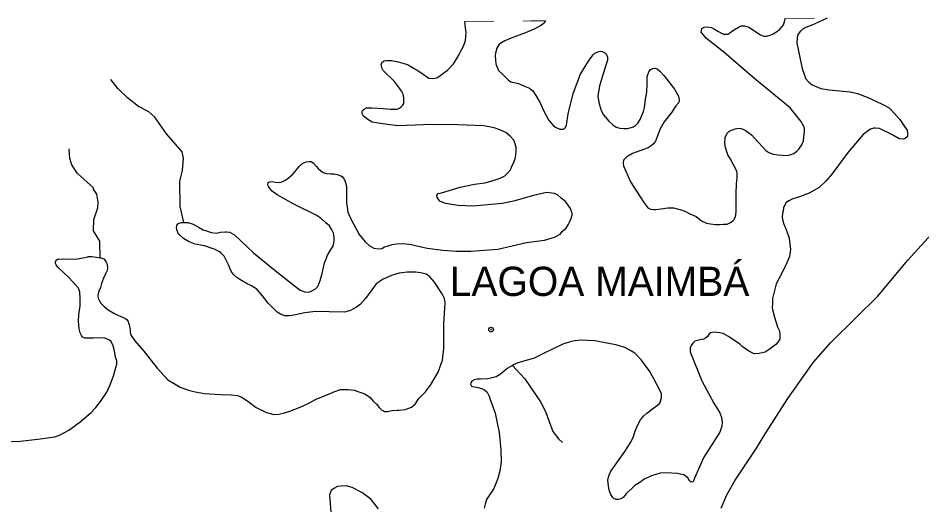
# Model space of a CAD drawing. Extents: x 317.8 to 344.1, y 7676.8 to 7704.8.
# Drawn here: x 334.107 to 337.199, y 7703.031 to 7704.701 of the extents above; entities that cross this region are included whole.
import ezdxf
from ezdxf.enums import TextEntityAlignment as Align

# ---------------------------------------------------------------- set-up
doc = ezdxf.new("R2010")
doc.units = 0
doc.header["$LTSCALE"] = 0.032
doc.header["$PDMODE"] = 32
doc.header["$PDSIZE"] = 0.016
doc.linetypes.add('SHORT_DASHED', pattern=[2.7, 1.5, -1.2])
for name, color, linetype, lineweight in [('2', 7, 'Continuous', 25), ('62', 7, 'SHORT_DASHED', 13), ('7', 7, 'Continuous', 25)]:
    doc.layers.add(name, color=color, linetype=linetype, lineweight=lineweight)
doc.layers.add('61', color=7, linetype='Continuous')

msp = doc.modelspace()

# ---------------------------------------------------------------- linework, layer by layer
at = {"layer": '2'}
for points in [[(335.6243, 7704.5923), (335.6305, 7704.6048), (335.6378, 7704.6236), (335.6389, 7704.6371), (335.6399, 7704.6507), (335.6378, 7704.6674), (335.6349, 7704.6886)], [(335.9111, 7704.6913), (335.9062, 7704.6832), (335.898, 7704.6761), (335.8742, 7704.6638), (335.8433, 7704.6496), (335.8, 7704.6337), (335.7717, 7704.6231), (335.7584, 7704.6152), (335.7514, 7704.609), (335.7443, 7704.5975), (335.7399, 7704.5807), (335.739, 7704.571), (335.7408, 7704.5445), (335.7505, 7704.5215), (335.7638, 7704.5083), (335.7841, 7704.4879), (335.7929, 7704.4826), (335.8194, 7704.4765), (335.8397, 7704.4676), (335.8565, 7704.4605), (335.868, 7704.4517), (335.8777, 7704.4358), (335.8927, 7704.4102), (335.9051, 7704.3819), (335.921, 7704.3519), (335.9387, 7704.3324), (335.9475, 7704.3262), (335.9599, 7704.3209), (335.9652, 7704.3209), (335.9714, 7704.3209), (335.9758, 7704.3227), (335.9793, 7704.3262), (335.9829, 7704.3342), (335.9891, 7704.3731), (336.0058, 7704.4429), (336.0315, 7704.5083), (336.0509, 7704.5401), (336.0633, 7704.5595), (336.0739, 7704.5745), (336.0801, 7704.5807), (336.0898, 7704.5851), (336.0995, 7704.5869), (336.1048, 7704.586), (336.1145, 7704.5816), (336.1198, 7704.5763), (336.1234, 7704.5666), (336.1234, 7704.5569), (336.1189, 7704.5427), (336.096, 7704.4685), (336.0907, 7704.4332), (336.0942, 7704.412), (336.1013, 7704.3846), (336.1092, 7704.3695), (336.1278, 7704.3475), (336.141, 7704.336), (336.1534, 7704.3271), (336.1658, 7704.3236), (336.1799, 7704.3227), (336.1923, 7704.3227), (336.2091, 7704.3271), (336.2179, 7704.3324), (336.2267, 7704.3413), (336.2356, 7704.3536), (336.24, 7704.3651), (336.2462, 7704.381), (336.2497, 7704.3952), (336.2532, 7704.4226), (336.2577, 7704.4473), (336.2594, 7704.4747), (336.2594, 7704.4941), (336.2594, 7704.5012), (336.2647, 7704.5162), (336.27, 7704.5242), (336.278, 7704.5286), (336.285, 7704.5295), (336.2939, 7704.5268), (336.3027, 7704.5189), (336.3169, 7704.503), (336.3531, 7704.457), (336.3663, 7704.4332), (336.369, 7704.4208), (336.3672, 7704.412), (336.3575, 7704.4005), (336.3434, 7704.3784), (336.3177, 7704.3457), (336.3036, 7704.3218), (336.2948, 7704.298), (336.2877, 7704.2794), (336.2806, 7704.2706), (336.2727, 7704.2635), (336.263, 7704.2564), (336.2091, 7704.237), (336.1896, 7704.2264), (336.1826, 7704.2193), (336.1781, 7704.214)], [(336.8746, 7704.7006), (336.8303, 7704.6799), (336.7938, 7704.6653), (336.7823, 7704.6548), (336.775, 7704.6444), (336.7719, 7704.634), (336.7709, 7704.6152), (336.7896, 7704.5277), (336.7969, 7704.5048), (336.8011, 7704.4933), (336.8126, 7704.4808), (336.824, 7704.4724), (336.8532, 7704.4599), (336.8824, 7704.4547), (336.9178, 7704.4516), (336.9533, 7704.4485), (336.9793, 7704.4422), (337.0116, 7704.4297), (337.0398, 7704.4172), (337.0679, 7704.4036), (337.0867, 7704.3932), (337.0919, 7704.3891), (337.1232, 7704.3536), (337.1398, 7704.3296), (337.1482, 7704.3171), (337.1503, 7704.3067), (337.1503, 7704.3025), (337.1503, 7704.2952), (337.1419, 7704.289), (337.1346, 7704.2859), (337.1211, 7704.2869), (337.1023, 7704.2984), (337.0825, 7704.3088), (337.0742, 7704.313), (337.0606, 7704.3192), (337.0544, 7704.3223), (337.0408, 7704.3244), (337.0346, 7704.3234), (337.0231, 7704.3203), (337.0116, 7704.313), (336.9981, 7704.3025), (336.947, 7704.2421), (336.8907, 7704.166), (336.872, 7704.1441), (336.848, 7704.1212), (336.8136, 7704.1014), (336.7802, 7704.0889), (336.7573, 7704.0816), (336.7438, 7704.0753), (336.7344, 7704.0691), (336.7302, 7704.0618), (336.726, 7704.0513), (336.724, 7704.0409), (336.7219, 7704.0336), (336.7208, 7704.018), (336.7229, 7704.0065), (336.7271, 7703.9951), (336.7344, 7703.9773), (336.7448, 7703.9471), (336.75, 7703.9085), (336.7458, 7703.8846), (336.7365, 7703.8627), (336.7208, 7703.8304), (336.701, 7703.7918), (336.6875, 7703.7407), (336.6875, 7703.7261), (336.6864, 7703.7084), (336.6948, 7703.6771), (336.7052, 7703.6438), (336.7114, 7703.6302), (336.7125, 7703.6188), (336.7125, 7703.6021), (336.7062, 7703.5917), (336.6989, 7703.5833), (336.676, 7703.5667), (336.6625, 7703.5573), (336.6427, 7703.5531), (336.6249, 7703.5521), (336.6072, 7703.5604), (336.5843, 7703.5771), (336.5759, 7703.5844), (336.5374, 7703.6115), (336.5197, 7703.6209), (336.5072, 7703.624), (336.4873, 7703.6261), (336.4769, 7703.624), (336.4707, 7703.6198), (336.4655, 7703.6115), (336.4582, 7703.6052), (336.4519, 7703.6021), (336.4404, 7703.6), (336.43, 7703.5979), (336.4227, 7703.5948), (336.4154, 7703.5885), (336.4102, 7703.5802)], [(336.7136, 7704.6629), (336.7206, 7704.6717), (336.7251, 7704.6779), (336.7295, 7704.6876), (336.7313, 7704.6993)], [(336.2612, 7704.0515), (336.2709, 7704.047), (336.2806, 7704.0453), (336.2877, 7704.0453), (336.3071, 7704.0479), (336.3301, 7704.0515), (336.3487, 7704.0515), (336.3707, 7704.0453), (336.3875, 7704.04), (336.4052, 7704.0311), (336.4264, 7704.0214), (336.445, 7704.0073), (336.4626, 7703.9993), (336.4759, 7703.9967), (336.4927, 7703.994), (336.5068, 7703.994), (336.5201, 7703.9949), (336.5333, 7703.9958), (336.5448, 7704.0011), (336.5528, 7704.0064), (336.5554, 7704.0099), (336.5616, 7704.0205), (336.5634, 7704.0364), (336.5642, 7704.0992), (336.5651, 7704.1345), (336.5669, 7704.1531), (336.5669, 7704.1681), (336.566, 7704.1769), (336.543, 7704.2202), (336.536, 7704.2308), (336.5333, 7704.2397), (336.5263, 7704.2609), (336.5254, 7704.2759), (336.5263, 7704.2874), (336.5263, 7704.2918), (336.5333, 7704.3068), (336.5386, 7704.313), (336.5422, 7704.3148), (336.5607, 7704.3218), (336.5722, 7704.3236), (336.581, 7704.3227), (336.5943, 7704.3174), (336.604, 7704.3103), (336.6164, 7704.3006), (336.665, 7704.2476), (336.6756, 7704.2405), (336.6906, 7704.2344), (336.7074, 7704.2326), (336.7348, 7704.2308), (336.748, 7704.2326), (336.7604, 7704.237), (336.771, 7704.245), (336.7781, 7704.252), (336.7887, 7704.2671), (336.794, 7704.2803), (336.7957, 7704.2927), (336.7975, 7704.313), (336.7975, 7704.3218), (336.7957, 7704.3298), (336.7851, 7704.3475), (336.748, 7704.3934), (336.6287, 7704.4915), (336.521, 7704.5842), (336.4618, 7704.6302), (336.4494, 7704.6452), (336.4441, 7704.6523), (336.445, 7704.6585), (336.4467, 7704.6646), (336.4494, 7704.6673), (336.4547, 7704.67), (336.4662, 7704.6708), (336.4794, 7704.6682), (336.49, 7704.6629), (336.5033, 7704.6549), (336.5112, 7704.6496), (336.5201, 7704.6461), (336.5289, 7704.6452), (336.5377, 7704.6461), (336.5422, 7704.6496), (336.551, 7704.6567), (336.5607, 7704.6629), (336.5713, 7704.67), (336.5802, 7704.6735), (336.5837, 7704.6744), (336.5925, 7704.6744), (336.6075, 7704.67), (336.6164, 7704.6638), (336.6314, 7704.6532), (336.6464, 7704.6434), (336.6579, 7704.639), (336.6685, 7704.639), (336.68, 7704.6417), (336.6906, 7704.647), (336.7047, 7704.6558), (336.7136, 7704.6629)], [(335.5513, 7704.5037), (335.5763, 7704.5225), (335.5962, 7704.5444), (335.6076, 7704.5621), (335.616, 7704.5756), (335.6243, 7704.5923)], [(335.6556, 7703.9033), (335.7483, 7703.9096), (335.8463, 7703.9325), (335.9078, 7703.9409), (335.9422, 7703.9513), (335.961, 7703.9617), (335.9693, 7703.9711), (335.9818, 7703.9815), (335.9891, 7703.993), (335.9933, 7704.0023), (335.9985, 7704.0128), (336.0027, 7704.0263), (336.0027, 7704.0315), (335.9964, 7704.0493), (335.9797, 7704.0732), (335.9651, 7704.0847), (335.9526, 7704.0962), (335.9422, 7704.1003), (335.9151, 7704.1035), (335.8703, 7704.0941), (335.8015, 7704.0743), (335.7629, 7704.0659), (335.6639, 7704.0566), (335.6118, 7704.0597), (335.5701, 7704.0659), (335.5629, 7704.0683), (335.5492, 7704.0743), (335.544, 7704.0816), (335.5409, 7704.0878), (335.5399, 7704.0941), (335.5399, 7704.0951), (335.544, 7704.1003), (335.5555, 7704.1024), (335.6191, 7704.1222), (335.6681, 7704.1326), (335.7035, 7704.1368), (335.7327, 7704.1451), (335.7556, 7704.1524), (335.7723, 7704.1608), (335.7817, 7704.1702), (335.7911, 7704.1816), (335.7952, 7704.191), (335.8025, 7704.2077), (335.8077, 7704.2192), (335.8098, 7704.2317), (335.8109, 7704.2452), (335.8109, 7704.2588), (335.8067, 7704.2734), (335.8025, 7704.2827), (335.79, 7704.2963), (335.7754, 7704.3088), (335.7546, 7704.3182), (335.7358, 7704.3255), (335.7004, 7704.3317), (335.6107, 7704.3349), (335.5221, 7704.3359), (335.4075, 7704.3317), (335.37, 7704.3359), (335.3178, 7704.3442), (335.3001, 7704.3557), (335.2876, 7704.3661), (335.2845, 7704.3724), (335.2845, 7704.3786), (335.2855, 7704.3838), (335.2907, 7704.3891), (335.2991, 7704.3932), (335.3178, 7704.3932), (335.3554, 7704.3911), (335.3814, 7704.3891), (335.4033, 7704.3891), (335.4117, 7704.3922), (335.4179, 7704.3974), (335.4231, 7704.4026), (335.4263, 7704.4078), (335.4263, 7704.4162), (335.4263, 7704.4276), (335.4242, 7704.4401), (335.42, 7704.4495), (335.4117, 7704.461), (335.395, 7704.4839), (335.3564, 7704.5214), (335.3512, 7704.5298), (335.3502, 7704.5371), (335.3491, 7704.5433), (335.3533, 7704.5506), (335.3595, 7704.5548), (335.3679, 7704.5558), (335.3846, 7704.5558), (335.4075, 7704.5506), (335.4388, 7704.5412), (335.4815, 7704.5162), (335.5117, 7704.4954), (335.5263, 7704.4933), (335.5399, 7704.4964), (335.5513, 7704.5037)], [(334.6737, 7704.0013), (334.6872, 7704.0013), (334.706, 7703.9951), (334.7258, 7703.9836), (334.7394, 7703.9763), (334.7519, 7703.9721), (334.7675, 7703.9669), (334.7842, 7703.9648), (334.7988, 7703.968), (334.8154, 7703.969), (334.8196, 7703.969), (334.83, 7703.968), (334.8467, 7703.9586), (334.9124, 7703.8971), (334.9801, 7703.8418), (335.0354, 7703.7981), (335.0719, 7703.7699), (335.0875, 7703.7637), (335.1, 7703.7626), (335.1073, 7703.7647), (335.1146, 7703.7689), (335.124, 7703.7741), (335.1334, 7703.7845), (335.1407, 7703.8022), (335.1469, 7703.8272), (335.1552, 7703.8627), (335.1615, 7703.8794), (335.1646, 7703.8866), (335.1761, 7703.9065), (335.1844, 7703.92), (335.1876, 7703.9304), (335.1886, 7703.9398), (335.1886, 7703.9523), (335.1855, 7703.9648), (335.1803, 7703.9763), (335.1719, 7703.9898), (335.1594, 7704.0003), (335.1438, 7704.0149), (335.1261, 7704.0263), (335.05, 7704.0638), (334.9926, 7704.0962), (334.976, 7704.1087), (334.9676, 7704.117), (334.9635, 7704.1243), (334.9614, 7704.1285), (334.9614, 7704.1326), (334.9624, 7704.1379), (334.9666, 7704.1399), (334.976, 7704.141), (334.9864, 7704.1389), (334.9989, 7704.1379), (335.0072, 7704.1389), (335.0197, 7704.1451), (335.0312, 7704.1524), (335.0468, 7704.166), (335.0583, 7704.1806), (335.0635, 7704.1868), (335.0687, 7704.1931), (335.0781, 7704.2014), (335.0865, 7704.2066), (335.0927, 7704.2087), (335.1021, 7704.2098), (335.1094, 7704.2098), (335.1177, 7704.2046), (335.1271, 7704.1941), (335.1334, 7704.1858), (335.1427, 7704.1775), (335.15, 7704.1722), (335.1615, 7704.1691), (335.1771, 7704.1681), (335.1865, 7704.1681), (335.199, 7704.165), (335.2115, 7704.1608), (335.2167, 7704.1577), (335.224, 7704.1472), (335.2261, 7704.142), (335.2293, 7704.1306), (335.2303, 7704.1222), (335.2303, 7704.1055), (335.2303, 7704.0889), (335.2303, 7704.068), (335.2324, 7704.0534), (335.2355, 7704.0367), (335.2438, 7704.0159), (335.2741, 7703.9596), (335.2939, 7703.9346), (335.3074, 7703.9221), (335.3241, 7703.9138), (335.3408, 7703.9106), (335.3512, 7703.9127), (335.3606, 7703.9179), (335.37, 7703.92), (335.3866, 7703.9263), (335.4012, 7703.9283), (335.4263, 7703.9294)], [(336.1781, 7704.214), (336.1773, 7704.2043), (336.1781, 7704.1946), (336.202, 7704.1398), (336.2479, 7704.0691), (336.2612, 7704.0515)], [(335.2647, 7703.7115), (335.2438, 7703.7001), (335.223, 7703.6949), (335.1709, 7703.6959), (335.15, 7703.6969), (335.1156, 7703.6959), (335.0875, 7703.6917), (335.0562, 7703.6855), (335.0354, 7703.6813), (335.0197, 7703.6813), (335.0041, 7703.6876), (334.9926, 7703.6938), (334.9624, 7703.7251), (334.9426, 7703.7501), (334.9238, 7703.773), (334.9051, 7703.7845), (334.8905, 7703.7918), (334.8707, 7703.8022), (334.8561, 7703.8116), (334.8436, 7703.8231), (334.8363, 7703.8345), (334.8269, 7703.8564), (334.8123, 7703.8856), (334.7998, 7703.8981), (334.7936, 7703.9023), (334.781, 7703.9085), (334.7446, 7703.921), (334.7123, 7703.9273), (334.6893, 7703.9356), (334.6726, 7703.9461), (334.6539, 7703.9638), (334.6497, 7703.9773), (334.6487, 7703.9846), (334.6497, 7703.9909), (334.6528, 7703.9961), (334.6581, 7703.9992), (334.6643, 7704.0013), (334.6737, 7704.0013)], [(336.5128, 7703.0234), (336.5313, 7703.0693), (336.5604, 7703.1196), (336.6336, 7703.2289), (336.6654, 7703.2818), (336.7404, 7703.3991), (336.8277, 7703.5235), (336.8876, 7703.5905), (336.9741, 7703.676), (337.0473, 7703.7475), (337.1505, 7703.8727), (337.2439, 7703.9741)], [(335.4263, 7703.9294), (335.4513, 7703.9263), (335.5065, 7703.9138), (335.5597, 7703.9065), (335.6066, 7703.9033), (335.6556, 7703.9033)], [(334.0535, 7703.2508), (334.114, 7703.2529), (334.1744, 7703.2602), (334.2328, 7703.2675), (334.2505, 7703.2748), (334.2807, 7703.2904), (334.3193, 7703.3186), (334.3568, 7703.3509), (334.3725, 7703.3686), (334.3881, 7703.3884), (334.41, 7703.4207), (334.4214, 7703.4457), (334.4329, 7703.476), (334.4402, 7703.501), (334.4444, 7703.5166), (334.4444, 7703.5281), (334.4402, 7703.5406), (334.436, 7703.5625), (334.4319, 7703.5792), (334.4246, 7703.5938), (334.4173, 7703.6), (334.4037, 7703.6052), (334.387, 7703.6063), (334.3652, 7703.6052), (334.3485, 7703.6052), (334.3349, 7703.6052), (334.3276, 7703.6083), (334.3235, 7703.6146), (334.3193, 7703.624), (334.3162, 7703.6375), (334.3141, 7703.65), (334.313, 7703.6636), (334.3141, 7703.6855), (334.3193, 7703.7157), (334.3193, 7703.7407), (334.3183, 7703.7626), (334.313, 7703.7762), (334.2818, 7703.8116), (334.2588, 7703.8335), (334.2484, 7703.8429), (334.2422, 7703.8481), (334.2369, 7703.8564), (334.2349, 7703.8606), (334.2349, 7703.8668), (334.2369, 7703.8721), (334.2411, 7703.8752), (334.2453, 7703.8762), (334.2609, 7703.8773), (334.3037, 7703.8762), (334.3412, 7703.8825), (334.3474, 7703.8846), (334.3589, 7703.8846), (334.3745, 7703.8825), (334.3871, 7703.8808)], [(334.3871, 7703.8808), (334.3902, 7703.8804), (334.3996, 7703.8773), (334.4048, 7703.871), (334.4079, 7703.8658), (334.411, 7703.8585), (334.4121, 7703.8439), (334.411, 7703.8366), (334.4058, 7703.8252), (334.3985, 7703.8106), (334.3923, 7703.7928), (334.3881, 7703.7793), (334.3829, 7703.7657), (334.3797, 7703.7511), (334.3808, 7703.7418), (334.385, 7703.7334), (334.3902, 7703.7251), (334.4016, 7703.7136), (334.4152, 7703.7022), (334.434, 7703.6907), (334.4506, 7703.6824), (334.4558, 7703.6803), (334.4746, 7703.673), (334.4798, 7703.6678), (334.4829, 7703.6625), (334.4871, 7703.6511), (334.4902, 7703.6344), (334.4902, 7703.625), (334.4934, 7703.6146), (334.5059, 7703.5958), (334.5371, 7703.5604), (334.583, 7703.5031), (334.6195, 7703.4624), (334.6382, 7703.451), (334.6612, 7703.4374), (334.6893, 7703.427), (334.7123, 7703.4218), (334.7446, 7703.4155), (334.7998, 7703.4124), (334.8363, 7703.4113), (334.8571, 7703.4093), (334.8728, 7703.403), (334.8978, 7703.3863), (334.9218, 7703.3686), (334.9572, 7703.3509), (334.9812, 7703.3446), (334.9989, 7703.3457), (335.0177, 7703.3498), (335.0364, 7703.3551), (335.0719, 7703.3697), (335.0969, 7703.3811), (335.1261, 7703.3968), (335.1459, 7703.4051), (335.1719, 7703.4145), (335.1865, 7703.4218), (335.2094, 7703.4301), (335.2178, 7703.4301), (335.2365, 7703.4301), (335.2564, 7703.427), (335.2793, 7703.4197), (335.2949, 7703.4134), (335.3116, 7703.402), (335.322, 7703.3895), (335.3335, 7703.3801), (335.3418, 7703.3686), (335.3502, 7703.3603), (335.3606, 7703.354), (335.371, 7703.354), (335.3866, 7703.3582), (335.4054, 7703.3592), (335.4096, 7703.3592), (335.4315, 7703.3613), (335.444, 7703.3655), (335.4523, 7703.3697), (335.4606, 7703.3759), (335.4648, 7703.3801), (335.4784, 7703.3988), (335.5003, 7703.4218), (335.518, 7703.4447), (335.544, 7703.4895), (335.5586, 7703.5302), (335.5638, 7703.5698), (335.5638, 7703.6542), (335.568, 7703.7261), (335.5659, 7703.7407), (335.5576, 7703.7574), (335.5315, 7703.797), (335.5159, 7703.8158), (335.5034, 7703.8241), (335.4846, 7703.8293), (335.4659, 7703.8314), (335.4377, 7703.8314), (335.4106, 7703.8283), (335.3846, 7703.8199), (335.3564, 7703.8074)], [(335.3564, 7703.8074), (335.3314, 7703.7908), (335.3168, 7703.771), (335.2949, 7703.7407), (335.2782, 7703.722), (335.2647, 7703.7115)], [(336.5082, 7703.3498), (336.5134, 7703.3342), (336.5155, 7703.3175), (336.5144, 7703.304), (336.5072, 7703.2842), (336.4894, 7703.255), (336.453, 7703.1987), (336.4206, 7703.1268), (336.4165, 7703.1143), (336.4102, 7703.1122), (336.404, 7703.1174), (336.3987, 7703.1278), (336.3842, 7703.1383), (336.3623, 7703.1424), (336.3247, 7703.1445), (336.3039, 7703.1435), (336.2737, 7703.1341), (336.2487, 7703.1226), (336.2372, 7703.1143), (336.2174, 7703.1018), (336.1872, 7703.0726), (336.1767, 7703.0601), (336.1694, 7703.0559), (336.1601, 7703.0538), (336.1528, 7703.0538), (336.1455, 7703.057), (336.1413, 7703.0601), (336.135, 7703.0705), (336.1288, 7703.0851), (336.1267, 7703.1007), (336.1246, 7703.1195), (336.1277, 7703.1341), (336.135, 7703.1508), (336.1496, 7703.1706), (336.183, 7703.2175), (336.2038, 7703.2498), (336.2122, 7703.2685), (336.2195, 7703.2904), (336.2257, 7703.3061), (336.2361, 7703.3259), (336.2476, 7703.3394), (336.258, 7703.3488), (336.2862, 7703.3707), (336.2945, 7703.3759), (336.3018, 7703.3822), (336.3039, 7703.3853), (336.3081, 7703.402), (336.3081, 7703.4155), (336.2914, 7703.4489), (336.2685, 7703.4916), (336.2403, 7703.5302), (336.2226, 7703.5489), (336.2174, 7703.5541), (336.2059, 7703.5614), (336.183, 7703.5739), (336.1517, 7703.5823), (336.1152, 7703.5896), (336.0798, 7703.5958), (336.0548, 7703.5979), (336.0329, 7703.599), (336.01, 7703.5958), (335.9954, 7703.5927), (335.9704, 7703.5854), (335.9047, 7703.5531), (335.8724, 7703.5375), (335.8453, 7703.5291), (335.8161, 7703.5208), (335.8046, 7703.5156), (335.7982, 7703.5121)], [(336.4102, 7703.5802), (336.406, 7703.5719), (336.406, 7703.5583), (336.4467, 7703.4593), (336.4873, 7703.3832), (336.5082, 7703.3498)], [(335.7982, 7703.5121), (335.7796, 7703.502), (335.7567, 7703.4812), (335.7421, 7703.4728), (335.7244, 7703.4687), (335.7139, 7703.4666), (335.6889, 7703.4655), (335.6775, 7703.4655), (335.667, 7703.4624), (335.6597, 7703.4583), (335.6556, 7703.453), (335.6545, 7703.4478), (335.6577, 7703.4416), (335.6629, 7703.4395), (335.6681, 7703.4384), (335.6764, 7703.4374), (335.6962, 7703.4322), (335.7025, 7703.4291), (335.7119, 7703.4207), (335.7181, 7703.4072), (335.7233, 7703.3926), (335.7327, 7703.3686), (335.739, 7703.3488), (335.7525, 7703.2821), (335.7588, 7703.2237), (335.7598, 7703.182), (335.7546, 7703.1518), (335.7483, 7703.1257), (335.7348, 7703.0913), (335.7233, 7703.0736), (335.7098, 7703.0538), (335.7046, 7703.0371), (335.7014, 7703.0236)], [(335.3397, 7703.0215), (335.3137, 7703.0549), (335.2824, 7703.0778), (335.2501, 7703.0945), (335.2293, 7703.1007), (335.2126, 7703.0986), (335.2001, 7703.0976), (335.1865, 7703.0913), (335.1782, 7703.0841), (335.1719, 7703.0684), (335.1771, 7703.0111)]]:
    msp.add_lwpolyline(points, dxfattribs=at)
msp.add_point((335.7249, 7703.6346), dxfattribs=at)
at = {"layer": '62'}
msp.add_line((336.7313, 7704.6993), (336.8746, 7704.7006), dxfattribs=at)
msp.add_lwpolyline([(335.6349, 7704.6886), (335.8594, 7704.6908), (335.9111, 7704.6913)], dxfattribs=at)
at = {"layer": '7'}
for points in [[(334.6737, 7704.0013), (334.6615, 7704.0555), (334.6598, 7704.1422), (334.6695, 7704.1794), (334.6728, 7704.2218), (334.6678, 7704.2432), (334.6147, 7704.304), (334.5744, 7704.3621), (334.5537, 7704.3801), (334.519, 7704.3985), (334.4816, 7704.428), (334.4481, 7704.46), (334.4243, 7704.4903)], [(334.3871, 7703.8808), (334.386, 7703.9369), (334.3648, 7703.9728), (334.3663, 7704.0115), (334.3794, 7704.0513), (334.381, 7704.0709), (334.3762, 7704.0983), (334.3649, 7704.1147), (334.3645, 7704.1196), (334.3103, 7704.1689), (334.2909, 7704.1987), (334.2833, 7704.2202), (334.2817, 7704.2535)], [(335.7982, 7703.5121), (335.8404, 7703.4661), (335.8947, 7703.3872), (335.9111, 7703.3543), (335.9361, 7703.2866), (335.9554, 7703.2606), (335.9696, 7703.2482)]]:
    msp.add_lwpolyline(points, dxfattribs=at)

# ---------------------------------------------------------------- texts
at = {"layer": '61'}
msp.add_text('LAGOA MAIMBÁ', height=0.1, dxfattribs=at).set_placement((336.0961, 7703.7498), align=Align.CENTER)

doc.saveas('drawing.dxf')
